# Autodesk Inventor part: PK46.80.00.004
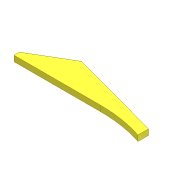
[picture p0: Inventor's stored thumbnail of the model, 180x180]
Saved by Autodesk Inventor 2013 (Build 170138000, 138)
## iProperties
Created: 2005-04
Part Number: PK46.80.00.004
Material: Steel, Mild
Document SubType Name: Modeling
Designer: salex
Manufacturer: Standard
Standards Organization: Custom
Density: 7.86 g/cm^3
Mass: 2233.21 g
Surface Area: 485.416 cm^2
Volume: 284.124 cm^3
Author: salex
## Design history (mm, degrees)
sketch "Эскиз1"
  geometry: L1 (0, 0)-(0, 15); L2 (0, 15)-(110, 80); L3 (110, 80)-(370, 10); L4 (370, 10)-(370, -20); L5 (243.826, 0)-(0, 0); A1 r 408 centre (243.826, -408) between (370, -20) and (243.826, 0)
  constraints: 10 end point, 2 point on circle, 1 centre point, 1 parallel, 1 perpendicular, 1 tangent, 1 vertical, 1 other
  dimensions: "d0" = 15 distance of L1.start L1.end; "d1" = 80 distance from line of L2.end L5; "d2" = 110 distance from line of L2.end L1; "d3" = 370 distance between parallel lines of L4 L1; "d4" = 408 radius of A1; "d5" = 20 distance from line of L4.end L5; "d6" = 30 distance of L3.end L4.end
extrude "Выдавливание1" new body sketch "Эскиз1" distance "d7" = 16; taper "d8" = 0 deg
body "Solid1"
